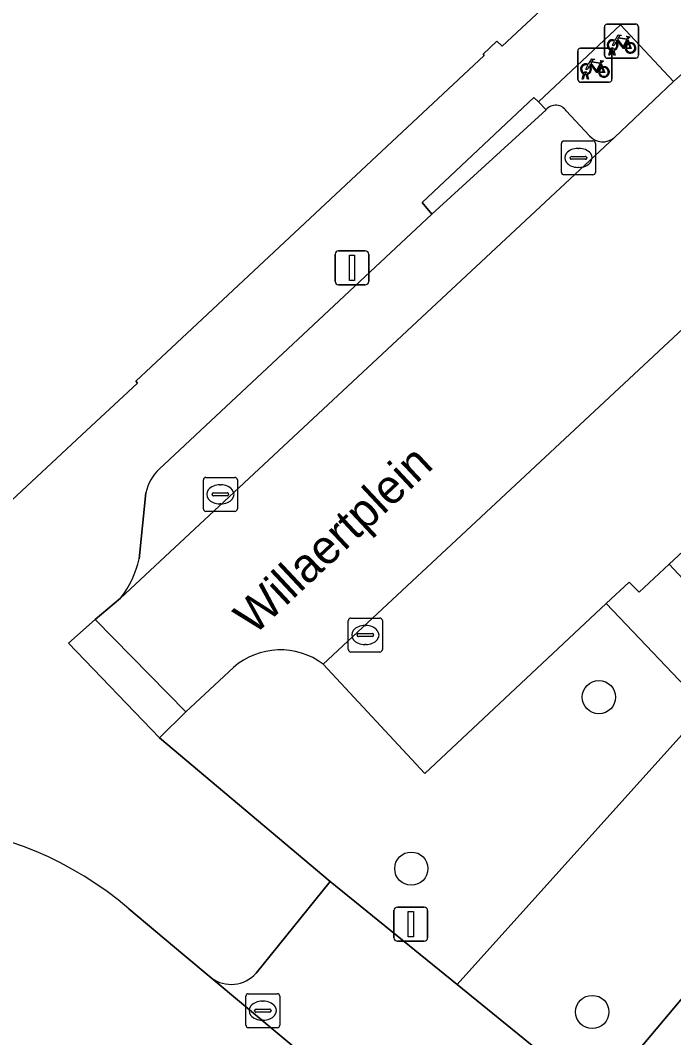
# Model space of a CAD drawing. Extents: x 159817 to 160765, y 380688 to 381638.
# Drawn here: x 160122.37 to 160141.58, y 381469.95 to 381499.89 of the extents above; entities that cross this region are included whole.
import ezdxf

# ---------------------------------------------------------------- set-up
doc = ezdxf.new("R2010")
doc.units = 0
for name, color, linetype in [('IMGEO_Boom', 7, 'Continuous'), ('IMGEO_Fietsenrek', 7, 'Continuous'), ('IMGEO_Groenvoorziening', 7, 'Continuous'), ('IMGEO_Kolk', 7, 'Continuous'), ('IMGEO_Lichtmast', 7, 'Continuous'), ('IMGEO_Openbare_ruimte_label', 7, 'Continuous'), ('IMGEO_Pand', 7, 'Continuous'), ('IMGEO_Parkeervlak_open', 7, 'Continuous'), ('IMGEO_Rijbaan_lokaal_open', 7, 'Continuous'), ('IMGEO_Voetpad_gesloten', 7, 'Continuous'), ('IMGEO_Voetpad_open', 7, 'Continuous')]:
    doc.layers.add(name, color=color, linetype=linetype)

msp = doc.modelspace()

# ---------------------------------------------------------------- linework, layer by layer
at = {"layer": 'IMGEO_Boom'}
for centre in [(160139.386, 381479.973), (160133.868, 381474.927), (160139.19, 381470.71)]:
    msp.add_circle(centre, 0.489, dxfattribs=at)
at = {"layer": 'IMGEO_Fietsenrek'}
for p, q in [((160139.548, 381498.85), (160139.548, 381499.691)), ((160139.548, 381499.691), (160139.548, 381498.85)), ((160139.623, 381499.775), (160140.464, 381499.775)), ((160140.464, 381499.775), (160139.623, 381499.775)), ((160140.548, 381499.7), (160140.548, 381498.859)), ((160140.548, 381498.859), (160140.548, 381499.7)), ((160140.235, 381499.324), (160140.271, 381499.229)), ((160138.766, 381498.143), (160138.766, 381498.984)), ((160138.766, 381498.984), (160138.766, 381498.143)), ((160138.841, 381499.068), (160139.682, 381499.068)), ((160139.682, 381499.068), (160138.841, 381499.068)), ((160139.675, 381498.859), (160139.714, 381499.019)), ((160139.744, 381499.007), (160139.709, 381498.859)), ((160139.766, 381498.993), (160139.766, 381498.152)), ((160139.766, 381498.152), (160139.766, 381498.993)), ((160139.786, 381499.031), (160139.785, 381499.035)), ((160139.827, 381498.859), (160139.793, 381499.001)), ((160139.817, 381499.042), (160139.818, 381499.035)), ((160139.825, 381499.005), (160139.86, 381498.859)), ((160139.453, 381498.617), (160139.489, 381498.522)), ((160140.473, 381498.775), (160139.632, 381498.775)), ((160139.632, 381498.775), (160140.473, 381498.775)), ((160139.709, 381498.859), (160139.675, 381498.859)), ((160139.86, 381498.859), (160139.827, 381498.859)), ((160138.893, 381498.152), (160138.932, 381498.312)), ((160138.962, 381498.3), (160138.927, 381498.152)), ((160139.004, 381498.324), (160139.003, 381498.328)), ((160139.045, 381498.152), (160139.011, 381498.294)), ((160139.035, 381498.335), (160139.036, 381498.328)), ((160139.043, 381498.298), (160139.078, 381498.152)), ((160139.691, 381498.068), (160138.85, 381498.068)), ((160138.85, 381498.068), (160139.691, 381498.068)), ((160138.927, 381498.152), (160138.893, 381498.152)), ((160139.078, 381498.152), (160139.045, 381498.152))]:
    msp.add_line(p, q, dxfattribs=at)
for points in [[(160139.882, 381499.249), (160139.83, 381499.159), (160139.79, 381499.134), (160139.791, 381499.181), (160139.846, 381499.275)], [(160139.861, 381499.301), (160139.956, 381499.465), (160140.042, 381499.451), (160140.044, 381499.442), (160139.988, 381499.431), (160139.961, 381499.386), (160140.217, 381499.345)], [(160140.157, 381499.057), (160140.107, 381499.057), (160139.916, 381499.308), (160139.897, 381499.276)], [(160140.204, 381499.32), (160139.947, 381499.361), (160139.93, 381499.332), (160140.097, 381499.112), (160140.204, 381499.32)], [(160140.252, 381499.222), (160140.222, 381499.299), (160140.113, 381499.081), (160140.156, 381499.081)], [(160140.186, 381499.081), (160140.306, 381499.08), (160140.262, 381499.194)], [(160140.282, 381499.201), (160140.337, 381499.056), (160140.187, 381499.056)], [(160140.217, 381499.345), (160140.242, 381499.394), (160140.236, 381499.398), (160140.213, 381499.402), (160140.201, 381499.409), (160140.2, 381499.412), (160140.202, 381499.417), (160140.297, 381499.402), (160140.299, 381499.392), (160140.289, 381499.379), (160140.277, 381499.373), (160140.263, 381499.379), (160140.235, 381499.324)], [(160139.079, 381498.594), (160139.174, 381498.758), (160139.26, 381498.744), (160139.262, 381498.735), (160139.206, 381498.724), (160139.179, 381498.679), (160139.435, 381498.638)], [(160139.375, 381498.35), (160139.325, 381498.35), (160139.134, 381498.601), (160139.115, 381498.569)], [(160139.422, 381498.613), (160139.165, 381498.654), (160139.148, 381498.625), (160139.315, 381498.405), (160139.422, 381498.613)], [(160139.435, 381498.638), (160139.46, 381498.687), (160139.454, 381498.691), (160139.431, 381498.695), (160139.419, 381498.702), (160139.418, 381498.705), (160139.42, 381498.71), (160139.515, 381498.695), (160139.517, 381498.685), (160139.507, 381498.672), (160139.495, 381498.666), (160139.481, 381498.672), (160139.453, 381498.617)], [(160139.1, 381498.542), (160139.048, 381498.452), (160139.008, 381498.427), (160139.009, 381498.474), (160139.064, 381498.568)], [(160139.47, 381498.515), (160139.44, 381498.592), (160139.331, 381498.374), (160139.374, 381498.374)], [(160139.404, 381498.374), (160139.524, 381498.373), (160139.48, 381498.487)], [(160139.5, 381498.494), (160139.555, 381498.349), (160139.405, 381498.349)]]:
    msp.add_lwpolyline(points, dxfattribs=at)
for centre, radius, start, end in [((160139.626, 381499.697), 0.0779, 92.4484, 184.2845), ((160139.626, 381499.697), 0.0779, 92.4484, 184.2845), ((160140.47, 381499.697), 0.0779, 2.4484, 94.2845), ((160140.47, 381499.697), 0.0779, 2.4484, 94.2845), ((160139.788, 381499.16), 0.159, 62.6766, 242.1369), ((160139.788, 381499.16), 0.129, 63.3192, 238.903), ((160139.788, 381499.16), 0.129, 283.6043, 43.4302), ((160139.788, 381499.16), 0.159, 283.5766, 46.6042), ((160140.315, 381499.076), 0.159, 113.3408, 178.3217), ((160140.315, 381499.076), 0.159, 187.0065, 105.7708), ((160140.315, 381499.076), 0.129, 113.923, 177.9556), ((160140.315, 381499.076), 0.129, 188.6715, 104.5883), ((160138.844, 381498.99), 0.0779, 92.4484, 184.2845), ((160138.844, 381498.99), 0.0779, 92.4484, 184.2845), ((160139.688, 381498.99), 0.0779, 2.4484, 94.2845), ((160139.688, 381498.99), 0.0779, 2.4484, 94.2845), ((160139.768, 381499.031), 0.0499, 12.8025, 158.6934), ((160139.788, 381499.16), 0.159, 253.9967, 271.7867), ((160139.768, 381499.031), 0.0174, 12.8025, 163.4502), ((160139.788, 381499.16), 0.129, 253.415, 269.0204), ((160139.006, 381498.453), 0.159, 62.6766, 242.1369), ((160139.626, 381498.853), 0.0779, 182.4484, 274.2845), ((160139.626, 381498.853), 0.0779, 182.4484, 274.2845), ((160140.47, 381498.853), 0.0779, 272.4484, 4.2845), ((160140.47, 381498.853), 0.0779, 272.4484, 4.2845), ((160139.006, 381498.453), 0.129, 63.3192, 238.903), ((160138.986, 381498.324), 0.0499, 12.8025, 158.6934), ((160139.006, 381498.453), 0.159, 253.9967, 271.7867), ((160138.986, 381498.324), 0.0174, 12.8025, 163.4502), ((160139.006, 381498.453), 0.129, 253.415, 269.0204), ((160139.006, 381498.453), 0.129, 283.6043, 43.4302), ((160139.006, 381498.453), 0.159, 283.5766, 46.6042), ((160139.533, 381498.369), 0.159, 113.3408, 178.3217), ((160139.533, 381498.369), 0.159, 187.0065, 105.7708), ((160139.533, 381498.369), 0.129, 113.923, 177.9556), ((160139.533, 381498.369), 0.129, 188.6715, 104.5883), ((160138.844, 381498.146), 0.0779, 182.4484, 274.2845), ((160138.844, 381498.146), 0.0779, 182.4484, 274.2845), ((160139.688, 381498.146), 0.0779, 272.4484, 4.2845), ((160139.688, 381498.146), 0.0779, 272.4484, 4.2845)]:
    msp.add_arc(centre, radius, start, end, dxfattribs=at)
at = {"layer": 'IMGEO_Groenvoorziening'}
msp.add_lwpolyline([(160151.334, 381493.06), (160141.452, 381483.881), (160144.181, 381480.96), (160153.516, 381490.785)], close=True, dxfattribs=at)
for points in [[(160128.635, 381480.849), (160127.24, 381479.545), (160126.464, 381478.778), (160131.485, 381474.55), (160135.22, 381471.513), (160142.527, 381479.647), (160139.598, 381482.725), (160134.268, 381477.724), (160131.28, 381480.942)], [(160145.397, 381476.452), (160142.913, 381479.241), (160142.527, 381479.647), (160135.22, 381471.513), (160137.58, 381469.594), (160139.165, 381468.211), (160139.317, 381468.118), (160140.189, 381469.158), (160145.532, 381475.513)]]:
    msp.add_lwpolyline(points, dxfattribs=at)
msp.add_arc((160130.015, 381479.254), 2.109, 53.1538, 130.8737, dxfattribs=at)
at = {"layer": 'IMGEO_Kolk'}
for p, q in [((160138.283, 381495.415), (160138.283, 381496.267)), ((160138.358, 381496.341), (160139.21, 381496.341)), ((160139.284, 381496.267), (160139.284, 381495.415)), ((160138.771, 381496.121), (160138.796, 381496.121)), ((160138.542, 381495.835), (160138.542, 381495.847)), ((160138.98, 381495.798), (160138.582, 381495.798)), ((160138.585, 381495.884), (160138.983, 381495.884)), ((160139.026, 381495.847), (160139.026, 381495.835)), ((160139.21, 381495.341), (160138.358, 381495.341)), ((160138.794, 381495.561), (160138.769, 381495.561)), ((160127.753, 381485.513), (160127.753, 381486.365)), ((160127.828, 381486.439), (160128.68, 381486.439)), ((160128.754, 381486.365), (160128.754, 381485.513)), ((160128.241, 381486.219), (160128.266, 381486.219)), ((160128.012, 381485.933), (160128.012, 381485.945)), ((160128.45, 381485.896), (160128.052, 381485.896)), ((160128.055, 381485.982), (160128.453, 381485.982)), ((160128.496, 381485.945), (160128.496, 381485.933)), ((160128.68, 381485.439), (160127.828, 381485.439)), ((160128.264, 381485.659), (160128.239, 381485.659)), ((160132.016, 381481.374), (160132.016, 381482.226)), ((160132.091, 381482.3), (160132.943, 381482.3)), ((160133.017, 381482.226), (160133.017, 381481.374)), ((160132.318, 381481.843), (160132.716, 381481.843)), ((160132.504, 381482.08), (160132.529, 381482.08)), ((160132.275, 381481.794), (160132.275, 381481.806)), ((160132.713, 381481.757), (160132.315, 381481.757)), ((160132.759, 381481.806), (160132.759, 381481.794)), ((160132.943, 381481.3), (160132.091, 381481.3)), ((160132.527, 381481.52), (160132.502, 381481.52)), ((160129, 381470.32), (160129, 381471.172)), ((160129.075, 381471.246), (160129.927, 381471.246)), ((160130.001, 381471.172), (160130.001, 381470.32)), ((160129.302, 381470.789), (160129.7, 381470.789)), ((160129.488, 381471.026), (160129.513, 381471.026)), ((160129.259, 381470.74), (160129.259, 381470.752)), ((160129.697, 381470.703), (160129.299, 381470.703)), ((160129.511, 381470.466), (160129.486, 381470.466)), ((160129.743, 381470.752), (160129.743, 381470.74)), ((160129.927, 381470.246), (160129.075, 381470.246))]:
    msp.add_line(p, q, dxfattribs=at)
for points in [[(160138.283, 381495.415), (160138.283, 381496.267)], [(160138.358, 381496.341), (160139.21, 381496.341)], [(160139.284, 381496.267), (160139.284, 381495.415)], [(160139.21, 381495.341), (160138.358, 381495.341)], [(160127.753, 381485.513), (160127.753, 381486.365)], [(160127.828, 381486.439), (160128.68, 381486.439)], [(160128.754, 381486.365), (160128.754, 381485.513)], [(160128.68, 381485.439), (160127.828, 381485.439)], [(160132.016, 381481.374), (160132.016, 381482.226)], [(160132.091, 381482.3), (160132.943, 381482.3)], [(160133.017, 381482.226), (160133.017, 381481.374)], [(160132.943, 381481.3), (160132.091, 381481.3)], [(160129, 381470.32), (160129, 381471.172)], [(160129.075, 381471.246), (160129.927, 381471.246)], [(160130.001, 381471.172), (160130.001, 381470.32)], [(160129.927, 381470.246), (160129.075, 381470.246)]]:
    msp.add_lwpolyline(points, dxfattribs=at)
for centre, radius, start, end in [((160138.36, 381496.265), 0.0765, 91.552, 178.448), ((160138.36, 381496.265), 0.0765, 91.552, 178.448), ((160139.208, 381496.265), 0.0765, 1.552, 88.448), ((160139.208, 381496.265), 0.0765, 1.552, 88.448), ((160138.582, 381495.844), 0.0403, 85.8775, 175.7526), ((160138.579, 381495.834), 0.0366, 178.938, 274.7102), ((160138.983, 381495.841), 0.043, 264.8664, 352.4533), ((160138.987, 381495.846), 0.0386, 1.7309, 96.639), ((160138.36, 381495.417), 0.0765, 181.552, 268.448), ((160138.36, 381495.417), 0.0765, 181.552, 268.448), ((160139.208, 381495.417), 0.0765, 271.552, 358.448), ((160139.208, 381495.417), 0.0765, 271.552, 358.448), ((160127.83, 381486.363), 0.0765, 91.552, 178.448), ((160127.83, 381486.363), 0.0765, 91.552, 178.448), ((160128.678, 381486.363), 0.0765, 1.552, 88.448), ((160128.678, 381486.363), 0.0765, 1.552, 88.448), ((160128.052, 381485.942), 0.0403, 85.8775, 175.7526), ((160128.049, 381485.932), 0.0366, 178.938, 274.7102), ((160128.453, 381485.939), 0.043, 264.8664, 352.4533), ((160128.457, 381485.944), 0.0386, 1.7309, 96.639), ((160127.83, 381485.515), 0.0765, 181.552, 268.448), ((160127.83, 381485.515), 0.0765, 181.552, 268.448), ((160128.678, 381485.515), 0.0765, 271.552, 358.448), ((160128.678, 381485.515), 0.0765, 271.552, 358.448), ((160132.093, 381482.224), 0.0765, 91.552, 178.448), ((160132.093, 381482.224), 0.0765, 91.552, 178.448), ((160132.941, 381482.224), 0.0765, 1.552, 88.448), ((160132.941, 381482.224), 0.0765, 1.552, 88.448), ((160132.315, 381481.803), 0.0403, 85.8775, 175.7526), ((160132.72, 381481.805), 0.0386, 1.7309, 96.639), ((160132.312, 381481.793), 0.0366, 178.938, 274.7102), ((160132.716, 381481.8), 0.043, 264.8664, 352.4533), ((160132.093, 381481.376), 0.0765, 181.552, 268.448), ((160132.093, 381481.376), 0.0765, 181.552, 268.448), ((160132.941, 381481.376), 0.0765, 271.552, 358.448), ((160132.941, 381481.376), 0.0765, 271.552, 358.448), ((160129.077, 381471.17), 0.0765, 91.552, 178.448), ((160129.077, 381471.17), 0.0765, 91.552, 178.448), ((160129.925, 381471.17), 0.0765, 1.552, 88.448), ((160129.925, 381471.17), 0.0765, 1.552, 88.448), ((160129.299, 381470.749), 0.0403, 85.8775, 175.7526), ((160129.704, 381470.751), 0.0386, 1.7309, 96.639), ((160129.296, 381470.739), 0.0366, 178.938, 274.7102), ((160129.7, 381470.746), 0.043, 264.8664, 352.4533), ((160129.077, 381470.322), 0.0765, 181.552, 268.448), ((160129.077, 381470.322), 0.0765, 181.552, 268.448), ((160129.925, 381470.322), 0.0765, 271.552, 358.448), ((160129.925, 381470.322), 0.0765, 271.552, 358.448)]:
    msp.add_arc(centre, radius, start, end, dxfattribs=at)
for centre, major_axis, ratio, start_param, end_param in [((160138.77, 381495.841), (-0.387, 0.002), 0.722429, 4.712389, 7.853982), ((160138.795, 381495.841), (-0.39, 0.002), 0.717154, 1.570796, 4.712389), ((160128.24, 381485.939), (-0.387, 0.002), 0.722429, 4.712389, 7.853982), ((160128.265, 381485.939), (-0.39, 0.002), 0.717154, 1.570796, 4.712389), ((160132.503, 381481.8), (-0.387, 0.002), 0.722429, 4.712389, 7.853982), ((160132.528, 381481.8), (-0.39, 0.002), 0.717154, 1.570796, 4.712389), ((160129.487, 381470.746), (-0.387, 0.002), 0.722429, 4.712389, 7.853982), ((160129.512, 381470.746), (-0.39, 0.002), 0.717154, 1.570796, 4.712389)]:
    msp.add_ellipse(centre, major_axis=major_axis, ratio=ratio, start_param=start_param, end_param=end_param, dxfattribs=at)
at = {"layer": 'IMGEO_Lichtmast'}
for p, q in [((160131.626, 381492.204), (160131.626, 381493.004)), ((160131.626, 381493.004), (160131.626, 381492.204)), ((160131.726, 381493.104), (160132.516, 381493.104)), ((160132.516, 381493.104), (160131.726, 381493.104)), ((160132.616, 381493.004), (160132.616, 381492.204)), ((160132.616, 381492.204), (160132.616, 381493.004)), ((160132.516, 381492.104), (160131.726, 381492.104)), ((160131.726, 381492.104), (160132.516, 381492.104)), ((160133.458, 381473.793), (160134.248, 381473.793)), ((160134.248, 381473.793), (160133.458, 381473.793)), ((160133.358, 381472.893), (160133.358, 381473.693)), ((160133.358, 381473.693), (160133.358, 381472.893)), ((160134.348, 381473.693), (160134.348, 381472.893)), ((160134.348, 381472.893), (160134.348, 381473.693)), ((160134.248, 381472.793), (160133.458, 381472.793)), ((160133.458, 381472.793), (160134.248, 381472.793))]:
    msp.add_line(p, q, dxfattribs=at)
for points in [[(160132.046, 381492.979), (160132.196, 381492.979), (160132.196, 381492.229), (160132.046, 381492.229), (160132.046, 381492.979)], [(160133.778, 381473.668), (160133.928, 381473.668), (160133.928, 381472.918), (160133.778, 381472.918), (160133.778, 381473.668)]]:
    msp.add_lwpolyline(points, dxfattribs=at)
for centre, start, end in [((160131.726, 381493.004), 90, 180), ((160131.726, 381493.004), 90, 180), ((160132.516, 381493.004), 0, 90), ((160132.516, 381493.004), 360, 90), ((160131.726, 381492.204), 180, 270), ((160131.726, 381492.204), 180, 270), ((160132.516, 381492.204), 270, 0), ((160132.516, 381492.204), 270, 0), ((160133.458, 381473.693), 90, 180), ((160133.458, 381473.693), 90, 180), ((160134.248, 381473.693), 0, 90), ((160134.248, 381473.693), 360, 90), ((160133.458, 381472.893), 180, 270), ((160133.458, 381472.893), 180, 270), ((160134.248, 381472.893), 270, 0), ((160134.248, 381472.893), 270, 0)]:
    msp.add_arc(centre, 0.1, start, end, dxfattribs=at)
at = {"layer": 'IMGEO_Pand'}
msp.add_lwpolyline([(160105.284, 381501.642), (160110.69, 381494.11), (160116.633, 381487.426), (160119.898, 381483.7), (160124.176, 381487.689), (160125.819, 381489.209), (160125.767, 381489.274), (160136.009, 381498.857), (160135.978, 381498.89), (160136.384, 381499.272), (160136.541, 381499.13), (160158.414, 381519.521)], dxfattribs=at)
at = {"layer": 'IMGEO_Parkeervlak_open'}
for points in [[(160137.838, 381497.259), (160134.467, 381494.182), (160126.455, 381486.68)], [(160148.684, 381497.185), (160131.28, 381480.942), (160134.268, 381477.724), (160139.598, 381482.725), (160140.272, 381483.358), (160140.567, 381483.059), (160141.452, 381483.881), (160151.334, 381493.06), (160148.705, 381495.82)], [(160139.107, 381496.49), (160138.424, 381497.221)], [(160125.316, 381482.881), (160139.843, 381496.437)], [(160126.063, 381485.988), (160125.862, 381484.047)], [(160131.485, 381474.55), (160129.307, 381471.849)], [(160135.22, 381471.513), (160131.485, 381474.55)], [(160127.985, 381471.712), (160135.947, 381465.067)], [(160137.58, 381469.594), (160135.22, 381471.513)]]:
    msp.add_lwpolyline(points, dxfattribs=at)
for centre, radius, start, end in [((160138.117, 381497.029), 0.362, 32.0643, 140.5152), ((160139.502, 381496.842), 0.529, 221.6578, 310.1046), ((160127.321, 381485.732), 1.284, 132.4269, 168.5122), ((160123.049, 381484.654), 2.878, 321.9832, 347.8325), ((160128.57, 381472.512), 0.991, 233.8066, 318.0264)]:
    msp.add_arc(centre, radius, start, end, dxfattribs=at)
at = {"layer": 'IMGEO_Rijbaan_lokaal_open'}
for points in [[(160175.473, 381522.224), (160176.001, 381522.709), (160172.248, 381526.721), (160171.948, 381526.433), (160167.006, 381521.77), (160157.677, 381513.05), (160143.228, 381499.558), (160141.576, 381498.084), (160139.843, 381496.437), (160125.316, 381482.881), (160124.571, 381482.258), (160127.24, 381479.545), (160128.635, 381480.849)], [(160131.28, 381480.942), (160148.684, 381497.185), (160149.88, 381498.323), (160175.473, 381522.224)], [(160127.985, 381471.712), (160127.151, 381472.41), (160125.558, 381473.744)], [(160123.446, 381467.855), (160132.294, 381460.562), (160135.947, 381465.067), (160127.985, 381471.712)]]:
    msp.add_lwpolyline(points, dxfattribs=at)
msp.add_lwpolyline([(160126.464, 381478.778), (160127.24, 381479.545), (160124.571, 381482.258), (160123.788, 381481.558)], close=True, dxfattribs=at)
for centre, radius, start, end in [((160130.015, 381479.254), 2.109, 53.1538, 130.8737), ((160118.821, 381465.913), 10.33, 49.2944, 119.8795)]:
    msp.add_arc(centre, radius, start, end, dxfattribs=at)
at = {"layer": 'IMGEO_Voetpad_gesloten'}
for points in [[(160158.742, 381489.467), (160158.904, 381489.65), (160158.123, 381490.504), (160156.084, 381488.109), (160148.041, 381478.719), (160145.532, 381475.513), (160140.189, 381469.158), (160141.827, 381467.816), (160142.292, 381468.244), (160148.71, 381475.795), (160156.852, 381485.447), (160157.199, 381485.941)], [(160144.437, 381480.685), (160144.181, 381480.96), (160141.452, 381483.881), (160140.567, 381483.059), (160140.272, 381483.358), (160139.598, 381482.725), (160142.527, 381479.647), (160142.913, 381479.241), (160145.397, 381476.452)]]:
    msp.add_lwpolyline(points, dxfattribs=at)
at = {"layer": 'IMGEO_Voetpad_open'}
for points in [[(160126.455, 381486.68), (160134.467, 381494.182), (160134.183, 381494.526), (160137.473, 381497.617), (160137.605, 381497.488), (160140.016, 381499.752), (160141.576, 381498.084), (160143.228, 381499.558), (160141.59, 381501.281), (160156.169, 381514.856), (160156.251, 381514.784), (160163.641, 381521.648), (160166.333, 381521.56)], [(160158.414, 381519.521), (160136.541, 381499.13), (160136.384, 381499.272), (160135.978, 381498.89), (160136.009, 381498.857), (160125.767, 381489.274), (160125.819, 381489.209), (160124.176, 381487.689), (160119.898, 381483.7), (160119.953, 381483.625)], [(160141.576, 381498.084), (160140.016, 381499.752), (160137.605, 381497.488), (160137.838, 381497.259)], [(160139.843, 381496.437), (160141.576, 381498.084)], [(160138.424, 381497.221), (160139.107, 381496.49)], [(160125.862, 381484.047), (160126.063, 381485.988)], [(160126.464, 381478.778), (160123.788, 381481.558), (160124.571, 381482.258), (160125.316, 381482.881)], [(160129.307, 381471.849), (160131.485, 381474.55), (160126.464, 381478.778)], [(160125.558, 381473.744), (160127.151, 381472.41), (160127.985, 381471.712)]]:
    msp.add_lwpolyline(points, dxfattribs=at)
msp.add_lwpolyline([(160137.838, 381497.259), (160137.605, 381497.488), (160137.473, 381497.617), (160134.183, 381494.526), (160134.467, 381494.182)], close=True, dxfattribs=at)
for centre, radius, start, end in [((160138.117, 381497.029), 0.362, 32.0643, 140.5152), ((160139.502, 381496.842), 0.529, 221.6578, 310.1046), ((160127.321, 381485.732), 1.284, 132.4269, 168.5122), ((160123.049, 381484.654), 2.878, 321.9832, 347.8325), ((160118.821, 381465.913), 10.33, 49.2944, 119.8795), ((160128.57, 381472.512), 0.991, 233.8066, 318.0264)]:
    msp.add_arc(centre, radius, start, end, dxfattribs=at)

# ---------------------------------------------------------------- texts
at = {"layer": 'IMGEO_Openbare_ruimte_label'}
msp.add_text('Willaertplein', height=1, rotation=43.0949, dxfattribs=at).set_placement((160129.242, 381481.769))

doc.saveas('drawing.dxf')
